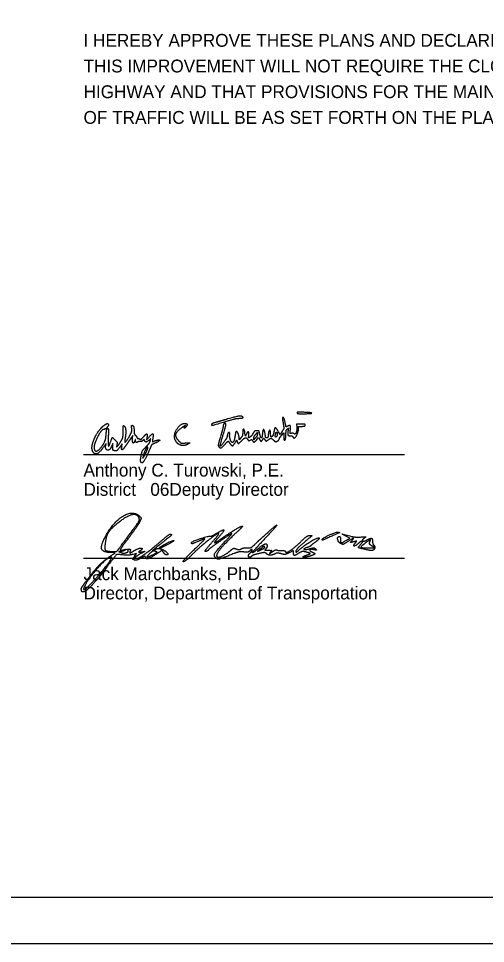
# Model space of a CAD drawing. Extents: x 0 to 34, y 0 to 22.
# Drawn here: x 23.82 to 28.91, y 0 to 10.08 of the extents above; entities that cross this region are included whole.
import ezdxf

# ---------------------------------------------------------------- set-up
doc = ezdxf.new("R2010")
doc.units = 0
for name, color, linetype in [('SH_Border', 7, 'Continuous'), ('SH_Cut_Line', 7, 'Continuous'), ('SH_Data', 7, 'Continuous'), ('SH_Text', 7, 'Continuous')]:
    doc.layers.add(name, color=color, linetype=linetype)

msp = doc.modelspace()

# ---------------------------------------------------------------- linework, layer by layer
at = {"layer": 'SH_Border'}
msp.add_lwpolyline([(1.5, 21.5), (33.5, 21.5), (33.5, 0.5), (1.5, 0.5)], close=True, dxfattribs=at)
at = {"layer": 'SH_Cut_Line'}
msp.add_lwpolyline([(0, 0), (34, 0), (34, 22), (0, 22)], close=True, dxfattribs=at)
at = {"layer": 'SH_Data'}
for p, q in [((24.528, 5.329), (28.028, 5.329)), ((24.528, 4.2), (28.028, 4.2))]:
    msp.add_line(p, q, dxfattribs=at)
at = {"layer": 'SH_Text'}
for p, q in [((25.929, 5.658), (25.929, 5.658)), ((25.216, 5.363), (25.216, 5.363)), ((25.569, 5.439), (25.569, 5.439)), ((25.157, 5.242), (25.157, 5.242)), ((24.99, 4.405), (24.99, 4.405)), ((27.129, 4.404), (27.129, 4.404)), ((25.311, 4.273), (25.311, 4.273)), ((25.356, 4.315), (25.356, 4.315)), ((25.727, 4.286), (25.727, 4.286)), ((26.504, 4.317), (26.504, 4.317)), ((27.582, 4.298), (27.582, 4.298))]:
    msp.add_line(p, q, dxfattribs=at)
for points in [[(26.897, 5.661), (26.85, 5.661), (26.852, 5.631)], [(26.303, 5.551), (26.292, 5.529), (26.288, 5.561)], [(26.69, 5.578), (26.67, 5.547), (26.652, 5.578)], [(26.687, 5.538), (26.711, 5.566), (26.711, 5.525)], [(24.77, 5.427), (24.774, 5.449), (24.757, 5.425)], [(24.847, 5.412), (24.847, 5.449), (24.832, 5.416)], [(24.946, 5.418), (24.951, 5.446), (24.923, 5.411)], [(25.062, 5.502), (25.065, 5.537), (25.032, 5.489)], [(25.219, 5.515), (25.214, 5.489), (25.242, 5.52)], [(25.256, 5.478), (25.262, 5.502), (25.242, 5.485)], [(26.244, 5.512), (26.224, 5.489), (26.224, 5.512)], [(26.418, 5.493), (26.437, 5.516), (26.446, 5.497)], [(24.891, 5.436), (24.886, 5.409), (24.902, 5.425)], [(27.393, 4.394), (27.43, 4.416), (27.389, 4.439)], [(24.843, 4.238), (24.873, 4.259), (24.835, 4.26)], [(25.085, 4.218), (25.107, 4.25), (25.065, 4.24)], [(26.453, 4.297), (26.423, 4.272), (26.464, 4.291)], [(27.642, 4.311), (27.698, 4.311), (27.669, 4.333)]]:
    msp.add_lwpolyline(points, dxfattribs=at)
for points in [[(26.068, 5.71), (26.193, 5.747), (26.264, 5.754), (26.263, 5.73)], [(26.93, 5.789), (26.864, 5.791), (26.855, 5.79), (26.855, 5.781)], [(26.855, 5.781), (26.855, 5.776), (26.886, 5.773), (26.933, 5.774)], [(26.933, 5.774), (27.018, 5.774), (27.015, 5.787), (26.93, 5.789)], [(24.744, 5.64), (24.77, 5.663), (24.799, 5.668), (24.799, 5.65)], [(24.799, 5.65), (24.799, 5.64), (24.771, 5.609), (24.761, 5.609)], [(25.052, 5.621), (25.046, 5.639), (25.063, 5.652), (25.072, 5.636)], [(25.52, 5.527), (25.52, 5.576), (25.595, 5.669), (25.633, 5.669)], [(25.633, 5.635), (25.642, 5.647), (25.64, 5.647), (25.619, 5.634)], [(25.633, 5.669), (25.652, 5.669), (25.66, 5.649), (25.647, 5.633)], [(25.941, 5.647), (25.93, 5.644), (25.927, 5.647), (25.929, 5.658)], [(25.929, 5.658), (25.93, 5.667), (25.942, 5.675), (25.959, 5.679)], [(26.225, 5.72), (26.193, 5.719), (26.141, 5.706), (25.941, 5.647)], [(25.959, 5.679), (25.975, 5.683), (26.024, 5.697), (26.068, 5.71)], [(26.039, 5.507), (26.074, 5.623), (26.083, 5.661), (26.077, 5.666)], [(26.077, 5.666), (26.069, 5.675), (26.051, 5.656), (26.05, 5.636)], [(26.263, 5.73), (26.263, 5.725), (26.248, 5.721), (26.225, 5.72)], [(26.699, 5.699), (26.713, 5.624), (26.712, 5.61), (26.69, 5.578)], [(26.702, 5.733), (26.696, 5.733), (26.695, 5.722), (26.699, 5.699)], [(26.731, 5.651), (26.717, 5.715), (26.71, 5.733), (26.702, 5.733)], [(26.753, 5.638), (26.738, 5.63), (26.735, 5.631), (26.731, 5.651)], [(26.782, 5.594), (26.786, 5.637), (26.777, 5.651), (26.753, 5.638)], [(26.943, 5.649), (26.943, 5.659), (26.933, 5.661), (26.897, 5.661)], [(26.913, 5.636), (26.934, 5.637), (26.943, 5.641), (26.943, 5.649)], [(24.64, 5.486), (24.66, 5.537), (24.711, 5.612), (24.744, 5.64)], [(24.748, 5.602), (24.736, 5.607), (24.688, 5.539), (24.663, 5.48)], [(24.757, 5.604), (24.758, 5.6), (24.754, 5.6), (24.748, 5.602)], [(24.761, 5.609), (24.758, 5.609), (24.756, 5.607), (24.757, 5.604)], [(24.762, 5.477), (24.767, 5.488), (24.773, 5.522), (24.775, 5.553)], [(24.775, 5.553), (24.778, 5.588), (24.783, 5.609), (24.79, 5.611)], [(24.79, 5.611), (24.798, 5.614), (24.8, 5.595), (24.798, 5.518)], [(24.939, 5.479), (24.956, 5.51), (24.959, 5.527), (24.959, 5.577)], [(24.959, 5.577), (24.959, 5.633), (24.966, 5.65), (24.98, 5.628)], [(24.98, 5.628), (24.988, 5.616), (24.989, 5.552), (24.983, 5.516)], [(25.015, 5.506), (25.043, 5.55), (25.059, 5.599), (25.052, 5.621)], [(25.072, 5.636), (25.076, 5.63), (25.079, 5.609), (25.079, 5.588)], [(25.079, 5.588), (25.079, 5.562), (25.084, 5.548), (25.095, 5.537)], [(25.181, 5.521), (25.21, 5.555), (25.225, 5.553), (25.219, 5.515)], [(25.242, 5.52), (25.277, 5.558), (25.29, 5.553), (25.283, 5.503)], [(25.619, 5.634), (25.544, 5.586), (25.523, 5.521), (25.568, 5.476)], [(25.647, 5.633), (25.633, 5.616), (25.619, 5.618), (25.633, 5.635)], [(26.05, 5.636), (26.049, 5.625), (26.037, 5.58), (26.024, 5.535)], [(26.121, 5.54), (26.125, 5.571), (26.101, 5.568), (26.095, 5.535)], [(26.192, 5.581), (26.189, 5.581), (26.184, 5.564), (26.181, 5.543)], [(26.224, 5.512), (26.223, 5.536), (26.203, 5.581), (26.192, 5.581)], [(26.263, 5.566), (26.263, 5.543), (26.258, 5.528), (26.244, 5.512)], [(26.288, 5.561), (26.282, 5.604), (26.263, 5.608), (26.263, 5.566)], [(26.329, 5.538), (26.332, 5.574), (26.318, 5.581), (26.303, 5.551)], [(26.375, 5.558), (26.366, 5.541), (26.351, 5.524), (26.342, 5.518)], [(26.415, 5.587), (26.396, 5.587), (26.388, 5.581), (26.375, 5.558)], [(26.384, 5.507), (26.384, 5.516), (26.392, 5.534), (26.403, 5.547)], [(26.403, 5.547), (26.422, 5.568), (26.423, 5.568), (26.423, 5.552)], [(26.423, 5.552), (26.423, 5.542), (26.415, 5.524), (26.404, 5.512)], [(26.449, 5.553), (26.441, 5.585), (26.438, 5.588), (26.415, 5.587)], [(26.478, 5.556), (26.475, 5.511), (26.461, 5.509), (26.449, 5.553)], [(26.508, 5.549), (26.501, 5.6), (26.482, 5.604), (26.478, 5.556)], [(26.526, 5.511), (26.516, 5.509), (26.512, 5.517), (26.508, 5.549)], [(26.542, 5.547), (26.54, 5.523), (26.536, 5.513), (26.526, 5.511)], [(26.567, 5.557), (26.567, 5.597), (26.545, 5.588), (26.542, 5.547)], [(26.605, 5.585), (26.597, 5.535), (26.567, 5.513), (26.567, 5.557)], [(26.652, 5.578), (26.629, 5.62), (26.611, 5.623), (26.605, 5.585)], [(26.637, 5.537), (26.628, 5.516), (26.615, 5.524), (26.62, 5.547)], [(26.62, 5.547), (26.623, 5.559), (26.627, 5.571), (26.628, 5.572)], [(26.628, 5.572), (26.634, 5.579), (26.641, 5.549), (26.637, 5.537)], [(26.734, 5.543), (26.735, 5.58), (26.74, 5.599), (26.749, 5.607)], [(26.749, 5.607), (26.761, 5.616), (26.762, 5.614), (26.757, 5.586)], [(26.757, 5.586), (26.751, 5.55), (26.761, 5.533), (26.788, 5.533)], [(26.795, 5.56), (26.781, 5.557), (26.78, 5.56), (26.782, 5.594)], [(26.821, 5.556), (26.815, 5.561), (26.804, 5.563), (26.795, 5.56)], [(26.852, 5.631), (26.855, 5.591), (26.835, 5.544), (26.821, 5.556)], [(26.823, 5.509), (26.838, 5.509), (26.871, 5.578), (26.871, 5.608)], [(26.871, 5.608), (26.871, 5.624), (26.874, 5.637), (26.877, 5.636)], [(26.877, 5.636), (26.881, 5.636), (26.897, 5.636), (26.913, 5.636)], [(24.634, 5.354), (24.619, 5.375), (24.621, 5.439), (24.64, 5.486)], [(24.663, 5.48), (24.646, 5.441), (24.641, 5.391), (24.651, 5.374)], [(24.651, 5.374), (24.664, 5.352), (24.737, 5.42), (24.762, 5.477)], [(24.798, 5.518), (24.797, 5.465), (24.798, 5.421), (24.801, 5.421)], [(24.801, 5.421), (24.804, 5.421), (24.812, 5.438), (24.82, 5.459)], [(24.82, 5.459), (24.84, 5.514), (24.844, 5.516), (24.872, 5.487)], [(24.872, 5.487), (24.893, 5.465), (24.896, 5.458), (24.891, 5.436)], [(24.902, 5.425), (24.911, 5.434), (24.927, 5.458), (24.939, 5.479)], [(24.983, 5.516), (24.974, 5.466), (24.987, 5.462), (25.015, 5.506)], [(25.032, 5.489), (25.014, 5.463), (24.991, 5.43), (24.981, 5.416)], [(25.087, 5.479), (25.075, 5.448), (25.06, 5.462), (25.062, 5.502)], [(25.095, 5.484), (25.095, 5.493), (25.092, 5.492), (25.087, 5.479)], [(25.095, 5.537), (25.104, 5.529), (25.111, 5.517), (25.111, 5.511)], [(25.121, 5.467), (25.108, 5.458), (25.096, 5.467), (25.095, 5.484)], [(25.111, 5.511), (25.111, 5.504), (25.114, 5.501), (25.117, 5.504)], [(25.117, 5.504), (25.119, 5.506), (25.129, 5.505), (25.138, 5.5)], [(25.146, 5.47), (25.138, 5.472), (25.127, 5.47), (25.121, 5.467)], [(25.138, 5.5), (25.153, 5.492), (25.158, 5.495), (25.181, 5.521)], [(25.175, 5.481), (25.167, 5.474), (25.154, 5.469), (25.146, 5.47)], [(25.194, 5.482), (25.19, 5.493), (25.188, 5.493), (25.175, 5.481)], [(25.242, 5.485), (25.217, 5.466), (25.201, 5.465), (25.194, 5.482)], [(25.209, 5.413), (25.231, 5.435), (25.252, 5.464), (25.256, 5.478)], [(25.307, 5.453), (25.276, 5.44), (25.268, 5.432), (25.253, 5.395)], [(25.283, 5.503), (25.278, 5.471), (25.279, 5.467), (25.291, 5.472)], [(25.291, 5.472), (25.351, 5.495), (25.365, 5.478), (25.307, 5.453)], [(25.569, 5.439), (25.548, 5.45), (25.519, 5.5), (25.52, 5.527)], [(25.568, 5.476), (25.591, 5.453), (25.595, 5.452), (25.64, 5.455)], [(25.64, 5.455), (25.666, 5.457), (25.687, 5.457), (25.687, 5.456)], [(25.687, 5.456), (25.687, 5.455), (25.677, 5.448), (25.664, 5.441)], [(26.024, 5.535), (26, 5.454), (25.995, 5.421), (26.005, 5.411)], [(26.077, 5.491), (26.025, 5.417), (26.013, 5.422), (26.039, 5.507)], [(26.072, 5.443), (26.092, 5.466), (26.107, 5.477), (26.109, 5.471)], [(26.095, 5.535), (26.092, 5.521), (26.084, 5.501), (26.077, 5.491)], [(26.109, 5.471), (26.111, 5.466), (26.119, 5.454), (26.127, 5.444)], [(26.15, 5.461), (26.139, 5.461), (26.119, 5.516), (26.121, 5.54)], [(26.127, 5.444), (26.144, 5.422), (26.162, 5.428), (26.183, 5.462)], [(26.181, 5.543), (26.176, 5.501), (26.161, 5.461), (26.15, 5.461)], [(26.183, 5.462), (26.197, 5.485), (26.198, 5.486), (26.203, 5.47)], [(26.203, 5.47), (26.211, 5.447), (26.221, 5.449), (26.252, 5.48)], [(26.252, 5.48), (26.282, 5.51), (26.303, 5.514), (26.318, 5.492)], [(26.318, 5.492), (26.327, 5.48), (26.332, 5.479), (26.345, 5.486)], [(26.342, 5.518), (26.328, 5.509), (26.327, 5.511), (26.329, 5.538)], [(26.345, 5.486), (26.359, 5.493), (26.363, 5.493), (26.369, 5.482)], [(26.369, 5.482), (26.38, 5.463), (26.396, 5.466), (26.418, 5.493)], [(26.404, 5.512), (26.385, 5.49), (26.384, 5.49), (26.384, 5.507)], [(26.446, 5.497), (26.457, 5.473), (26.468, 5.472), (26.481, 5.492)], [(26.481, 5.492), (26.49, 5.507), (26.491, 5.507), (26.504, 5.491)], [(26.504, 5.491), (26.517, 5.474), (26.518, 5.474), (26.54, 5.489)], [(26.54, 5.489), (26.567, 5.507), (26.578, 5.506), (26.6, 5.485)], [(26.6, 5.485), (26.608, 5.476), (26.62, 5.469), (26.625, 5.469)], [(26.625, 5.469), (26.637, 5.469), (26.663, 5.493), (26.663, 5.503)], [(26.663, 5.503), (26.663, 5.508), (26.674, 5.523), (26.687, 5.538)], [(26.711, 5.525), (26.711, 5.496), (26.714, 5.485), (26.721, 5.487)], [(26.721, 5.487), (26.728, 5.489), (26.732, 5.51), (26.734, 5.543)], [(26.788, 5.533), (26.798, 5.533), (26.808, 5.528), (26.81, 5.521)], [(26.81, 5.521), (26.813, 5.515), (26.819, 5.509), (26.823, 5.509)], [(24.757, 5.425), (24.707, 5.355), (24.655, 5.325), (24.634, 5.354)], [(24.805, 5.379), (24.786, 5.372), (24.765, 5.401), (24.77, 5.427)], [(24.832, 5.416), (24.824, 5.398), (24.812, 5.382), (24.805, 5.379)], [(24.861, 5.371), (24.851, 5.374), (24.847, 5.384), (24.847, 5.412)], [(24.923, 5.411), (24.894, 5.372), (24.884, 5.366), (24.861, 5.371)], [(24.981, 5.416), (24.957, 5.38), (24.94, 5.381), (24.946, 5.418)], [(25.16, 5.332), (25.167, 5.363), (25.177, 5.381), (25.209, 5.413)], [(25.253, 5.395), (25.228, 5.334), (25.18, 5.243), (25.171, 5.24)], [(25.23, 5.41), (25.223, 5.416), (25.186, 5.348), (25.18, 5.317)], [(25.186, 5.305), (25.192, 5.314), (25.206, 5.34), (25.216, 5.363)], [(25.216, 5.363), (25.226, 5.387), (25.232, 5.408), (25.23, 5.41)], [(25.664, 5.441), (25.637, 5.427), (25.596, 5.426), (25.569, 5.439)], [(26.005, 5.411), (26.018, 5.397), (26.041, 5.408), (26.072, 5.443)], [(25.157, 5.242), (25.149, 5.25), (25.15, 5.287), (25.16, 5.332)], [(25.171, 5.24), (25.166, 5.238), (25.16, 5.239), (25.157, 5.242)], [(25.18, 5.317), (25.175, 5.291), (25.175, 5.29), (25.186, 5.305)], [(24.779, 4.456), (24.865, 4.606), (25.073, 4.722), (25.139, 4.656)], [(25.13, 4.647), (25.104, 4.689), (24.978, 4.648), (24.883, 4.566)], [(24.99, 4.405), (25.112, 4.568), (25.144, 4.624), (25.13, 4.647)], [(25.139, 4.656), (25.158, 4.638), (25.158, 4.632), (25.139, 4.594)], [(24.883, 4.566), (24.816, 4.509), (24.777, 4.445), (24.766, 4.374)], [(25.139, 4.594), (25.128, 4.571), (25.077, 4.496), (25.024, 4.426)], [(26.033, 4.414), (26.113, 4.471), (26.244, 4.548), (26.26, 4.548)], [(26.26, 4.548), (26.265, 4.548), (26.224, 4.505), (26.168, 4.453)], [(26.487, 4.434), (26.562, 4.504), (26.628, 4.56), (26.634, 4.56)], [(26.634, 4.56), (26.639, 4.56), (26.587, 4.5), (26.518, 4.427)], [(24.835, 4.26), (24.737, 4.261), (24.714, 4.343), (24.779, 4.456)], [(25.369, 4.382), (25.419, 4.425), (25.465, 4.46), (25.47, 4.46)], [(25.47, 4.46), (25.495, 4.461), (25.472, 4.435), (25.386, 4.368)], [(26.002, 4.467), (25.992, 4.477), (25.782, 4.31), (25.704, 4.231)], [(25.705, 4.37), (25.705, 4.38), (25.892, 4.443), (25.908, 4.438)], [(26.142, 4.467), (26.093, 4.439), (25.905, 4.307), (25.891, 4.291)], [(25.908, 4.438), (25.914, 4.436), (25.943, 4.45), (25.974, 4.468)], [(25.924, 4.367), (25.97, 4.419), (26.005, 4.464), (26.002, 4.467)], [(25.974, 4.468), (26.052, 4.514), (26.065, 4.5), (26.005, 4.433)], [(26.168, 4.453), (26.069, 4.359), (25.979, 4.251), (25.979, 4.224)], [(26.077, 4.388), (26.123, 4.437), (26.152, 4.473), (26.142, 4.467)], [(26.895, 4.378), (26.94, 4.422), (26.977, 4.448), (26.995, 4.447)], [(26.995, 4.447), (27.019, 4.447), (27.016, 4.44), (26.967, 4.4)], [(27.129, 4.404), (27.129, 4.416), (27.282, 4.487), (27.301, 4.483)], [(27.301, 4.483), (27.322, 4.479), (27.323, 4.479), (27.201, 4.425)], [(27.389, 4.439), (27.346, 4.463), (27.345, 4.463), (27.448, 4.437)], [(27.448, 4.437), (27.469, 4.431), (27.514, 4.429), (27.548, 4.43)], [(24.766, 4.374), (24.755, 4.301), (24.776, 4.273), (24.844, 4.273)], [(24.844, 4.273), (24.891, 4.273), (24.895, 4.277), (24.99, 4.405)], [(25.024, 4.426), (24.972, 4.357), (24.929, 4.296), (24.929, 4.291)], [(25.108, 4.198), (25.131, 4.198), (25.257, 4.287), (25.369, 4.382)], [(25.386, 4.368), (25.293, 4.295), (25.271, 4.273), (25.315, 4.297)], [(25.356, 4.315), (25.376, 4.333), (25.508, 4.399), (25.513, 4.393)], [(25.513, 4.393), (25.519, 4.387), (25.377, 4.31), (25.359, 4.31)], [(25.786, 4.385), (25.723, 4.359), (25.704, 4.355), (25.705, 4.37)], [(25.727, 4.286), (25.798, 4.354), (25.854, 4.41), (25.85, 4.41)], [(25.85, 4.41), (25.847, 4.41), (25.818, 4.399), (25.786, 4.385)], [(25.858, 4.273), (25.848, 4.273), (25.877, 4.314), (25.924, 4.367)], [(26.005, 4.433), (25.977, 4.401), (25.954, 4.372), (25.954, 4.367)], [(25.954, 4.367), (25.954, 4.363), (25.99, 4.384), (26.033, 4.414)], [(25.97, 4.202), (25.945, 4.227), (25.973, 4.278), (26.077, 4.388)], [(26.312, 4.312), (26.345, 4.309), (26.369, 4.326), (26.487, 4.434)], [(26.518, 4.427), (26.388, 4.289), (26.356, 4.242), (26.439, 4.309)], [(26.439, 4.309), (26.487, 4.349), (26.529, 4.36), (26.529, 4.332)], [(26.729, 4.271), (26.729, 4.249), (26.825, 4.31), (26.895, 4.378)], [(26.967, 4.4), (26.893, 4.339), (26.842, 4.286), (26.842, 4.269)], [(26.876, 4.287), (26.93, 4.336), (27.077, 4.426), (27.094, 4.42)], [(27.06, 4.378), (27.033, 4.358), (27.008, 4.338), (27.004, 4.334)], [(27.094, 4.42), (27.102, 4.417), (27.087, 4.399), (27.06, 4.378)], [(27.201, 4.425), (27.138, 4.397), (27.129, 4.394), (27.129, 4.404)], [(27.33, 4.36), (27.304, 4.374), (27.293, 4.435), (27.317, 4.435)], [(27.317, 4.435), (27.324, 4.435), (27.329, 4.421), (27.329, 4.404)], [(27.329, 4.404), (27.329, 4.367), (27.344, 4.365), (27.393, 4.394)], [(27.405, 4.378), (27.365, 4.352), (27.352, 4.348), (27.33, 4.36)], [(27.453, 4.39), (27.477, 4.419), (27.461, 4.415), (27.405, 4.378)], [(27.472, 4.378), (27.439, 4.37), (27.437, 4.371), (27.453, 4.39)], [(27.492, 4.367), (27.507, 4.385), (27.505, 4.386), (27.472, 4.378)], [(27.521, 4.358), (27.489, 4.328), (27.466, 4.335), (27.492, 4.367)], [(27.546, 4.346), (27.577, 4.379), (27.555, 4.39), (27.521, 4.358)], [(27.582, 4.298), (27.527, 4.311), (27.522, 4.318), (27.546, 4.346)], [(27.548, 4.43), (27.603, 4.434), (27.608, 4.432), (27.588, 4.417)], [(27.589, 4.356), (27.546, 4.325), (27.563, 4.311), (27.642, 4.311)], [(27.588, 4.417), (27.559, 4.396), (27.582, 4.379), (27.616, 4.397)], [(27.65, 4.379), (27.66, 4.404), (27.651, 4.401), (27.589, 4.356)], [(27.616, 4.397), (27.656, 4.419), (27.679, 4.413), (27.679, 4.382)], [(27.669, 4.333), (27.649, 4.349), (27.643, 4.362), (27.65, 4.379)], [(27.679, 4.382), (27.679, 4.366), (27.686, 4.346), (27.694, 4.339)], [(27.694, 4.339), (27.701, 4.331), (27.704, 4.316), (27.7, 4.305)], [(24.592, 3.996), (24.669, 4.096), (24.749, 4.173), (24.843, 4.238)], [(24.924, 4.238), (24.89, 4.241), (24.879, 4.231), (24.802, 4.129)], [(24.936, 4.272), (24.913, 4.271), (24.914, 4.27), (24.94, 4.26)], [(25.065, 4.24), (25.025, 4.231), (25.002, 4.23), (24.924, 4.238)], [(24.929, 4.291), (24.929, 4.287), (24.945, 4.286), (24.964, 4.291)], [(24.979, 4.286), (24.969, 4.279), (24.949, 4.273), (24.936, 4.272)], [(24.94, 4.26), (24.97, 4.248), (25.026, 4.272), (25.009, 4.29)], [(24.964, 4.291), (24.989, 4.297), (24.993, 4.295), (24.979, 4.286)], [(25.009, 4.29), (25.004, 4.294), (25.01, 4.298), (25.022, 4.298)], [(25.022, 4.298), (25.037, 4.298), (25.042, 4.291), (25.037, 4.279)], [(25.037, 4.279), (25.029, 4.256), (25.041, 4.255), (25.074, 4.277)], [(25.074, 4.277), (25.102, 4.297), (25.167, 4.315), (25.167, 4.303)], [(25.152, 4.249), (25.101, 4.22), (25.081, 4.198), (25.108, 4.198)], [(25.145, 4.279), (25.126, 4.265), (25.128, 4.263), (25.161, 4.268)], [(25.167, 4.303), (25.167, 4.298), (25.157, 4.287), (25.145, 4.279)], [(25.161, 4.268), (25.198, 4.274), (25.198, 4.274), (25.152, 4.249)], [(25.316, 4.241), (25.248, 4.197), (25.21, 4.187), (25.202, 4.212)], [(25.258, 4.257), (25.213, 4.216), (25.225, 4.207), (25.283, 4.237)], [(25.311, 4.273), (25.293, 4.28), (25.277, 4.274), (25.258, 4.257)], [(25.283, 4.237), (25.329, 4.261), (25.333, 4.265), (25.311, 4.273)], [(25.315, 4.297), (25.328, 4.304), (25.351, 4.306), (25.368, 4.301)], [(25.401, 4.26), (25.384, 4.284), (25.382, 4.284), (25.316, 4.241)], [(25.359, 4.31), (25.354, 4.31), (25.353, 4.312), (25.356, 4.315)], [(25.368, 4.301), (25.404, 4.292), (25.463, 4.235), (25.436, 4.235)], [(25.436, 4.235), (25.426, 4.235), (25.411, 4.246), (25.401, 4.26)], [(25.617, 4.161), (25.607, 4.161), (25.656, 4.217), (25.727, 4.286)], [(25.891, 4.291), (25.883, 4.281), (25.868, 4.273), (25.858, 4.273)], [(26.169, 4.25), (26.023, 4.192), (25.988, 4.184), (25.97, 4.202)], [(25.998, 4.21), (26.019, 4.21), (26.101, 4.256), (26.137, 4.288)], [(26.137, 4.288), (26.157, 4.306), (26.17, 4.309), (26.194, 4.3)], [(26.275, 4.267), (26.246, 4.271), (26.206, 4.264), (26.169, 4.25)], [(26.194, 4.3), (26.214, 4.292), (26.233, 4.293), (26.249, 4.302)], [(26.249, 4.302), (26.262, 4.309), (26.291, 4.314), (26.312, 4.312)], [(26.344, 4.281), (26.329, 4.267), (26.307, 4.263), (26.275, 4.267)], [(26.341, 4.21), (26.323, 4.21), (26.327, 4.243), (26.348, 4.26)], [(26.367, 4.289), (26.367, 4.296), (26.357, 4.293), (26.344, 4.281)], [(26.348, 4.26), (26.359, 4.269), (26.367, 4.282), (26.367, 4.289)], [(26.436, 4.248), (26.397, 4.239), (26.363, 4.226), (26.359, 4.221)], [(26.52, 4.25), (26.509, 4.261), (26.489, 4.261), (26.436, 4.248)], [(26.504, 4.317), (26.504, 4.33), (26.48, 4.321), (26.453, 4.297)], [(26.464, 4.291), (26.486, 4.302), (26.504, 4.314), (26.504, 4.317)], [(26.514, 4.3), (26.503, 4.289), (26.509, 4.285), (26.541, 4.285)], [(26.529, 4.332), (26.529, 4.323), (26.523, 4.309), (26.514, 4.3)], [(26.616, 4.247), (26.585, 4.231), (26.538, 4.232), (26.52, 4.25)], [(26.541, 4.285), (26.579, 4.285), (26.581, 4.283), (26.565, 4.264)], [(26.565, 4.264), (26.553, 4.249), (26.56, 4.251), (26.587, 4.27)], [(26.587, 4.27), (26.609, 4.285), (26.629, 4.294), (26.633, 4.29)], [(26.681, 4.248), (26.654, 4.255), (26.631, 4.255), (26.616, 4.247)], [(26.633, 4.29), (26.637, 4.286), (26.66, 4.283), (26.685, 4.283)], [(26.77, 4.259), (26.732, 4.24), (26.714, 4.238), (26.681, 4.248)], [(26.685, 4.283), (26.709, 4.283), (26.729, 4.278), (26.729, 4.271)], [(26.817, 4.259), (26.817, 4.282), (26.816, 4.282), (26.77, 4.259)], [(26.879, 4.256), (26.834, 4.229), (26.817, 4.23), (26.817, 4.259)], [(26.842, 4.269), (26.842, 4.262), (26.857, 4.27), (26.876, 4.287)], [(26.962, 4.264), (26.923, 4.274), (26.906, 4.272), (26.879, 4.256)], [(26.97, 4.317), (26.921, 4.302), (26.94, 4.288), (26.992, 4.302)], [(26.948, 4.229), (26.962, 4.234), (26.982, 4.241), (26.992, 4.245)], [(26.992, 4.245), (27.003, 4.249), (26.992, 4.256), (26.962, 4.264)], [(27.004, 4.334), (27.001, 4.33), (26.986, 4.322), (26.97, 4.317)], [(26.992, 4.302), (27.03, 4.312), (27.045, 4.312), (27.058, 4.3)], [(27.039, 4.292), (27.002, 4.301), (26.989, 4.278), (27.023, 4.265)], [(27.023, 4.265), (27.054, 4.253), (27.045, 4.238), (26.998, 4.223)], [(27.058, 4.3), (27.07, 4.287), (27.067, 4.285), (27.039, 4.292)], [(27.7, 4.305), (27.692, 4.284), (27.651, 4.281), (27.582, 4.298)], [(24.835, 4.209), (24.814, 4.23), (24.596, 4.004), (24.55, 3.913)], [(24.62, 3.932), (24.687, 4.001), (24.843, 4.201), (24.835, 4.209)], [(25.084, 4.178), (25.066, 4.185), (25.066, 4.189), (25.085, 4.218)], [(25.151, 4.198), (25.125, 4.183), (25.095, 4.174), (25.084, 4.178)], [(25.202, 4.212), (25.199, 4.22), (25.18, 4.215), (25.151, 4.198)], [(25.704, 4.231), (25.667, 4.192), (25.627, 4.161), (25.617, 4.161)], [(25.979, 4.224), (25.979, 4.217), (25.988, 4.21), (25.998, 4.21)], [(26.359, 4.221), (26.356, 4.215), (26.348, 4.21), (26.341, 4.21)], [(26.998, 4.223), (26.952, 4.207), (26.904, 4.213), (26.948, 4.229)], [(24.802, 4.129), (24.65, 3.927), (24.504, 3.798), (24.504, 3.865)], [(24.504, 3.865), (24.504, 3.875), (24.544, 3.934), (24.592, 3.996)], [(24.55, 3.913), (24.518, 3.853), (24.55, 3.861), (24.62, 3.932)]]:
    msp.add_open_spline(points, degree=2, dxfattribs=at)

# ---------------------------------------------------------------- texts
for s, p in [('I HEREBY APPROVE THESE PLANS AND DECLARE THAT THE MAKING OF', (24.528, 9.773)), ('THIS IMPROVEMENT WILL NOT REQUIRE THE CLOSING TO TRAFFIC OF THE', (24.528, 9.493)), ('HIGHWAY AND THAT PROVISIONS FOR THE MAINTENANCE AND SAFETY', (24.528, 9.213)), ('OF TRAFFIC WILL BE AS SET FORTH ON THE PLANS AND ESTIMATES.', (24.528, 8.933)), ('Anthony C. Turowski, P.E.', (24.528, 5.089)), ('District       Deputy Director', (24.528, 4.879)), ('              06', (24.528, 4.879)), ('Jack Marchbanks, PhD', (24.528, 3.96)), ('Director, Department of Transportation', (24.528, 3.75))]:
    msp.add_text(s, height=0.14, dxfattribs=at).set_placement(p)

doc.saveas('drawing.dxf')
